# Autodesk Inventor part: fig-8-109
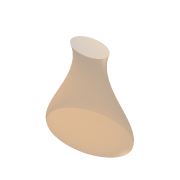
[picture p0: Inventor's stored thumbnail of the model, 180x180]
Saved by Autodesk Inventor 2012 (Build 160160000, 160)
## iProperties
Created: 2004-05
Part Number: fig-8-109
Document SubType Name: Modeling
Designer: CADCIM Technologies
Manufacturer: Standard
Standards Organization: Custom
Density: 1 g/cm^3
Material: Default
Author: CADCIM Technologies
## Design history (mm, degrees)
sketch "Sketch4"
  geometry: 1 further point; 1 other entity
  constraints: 2 other
workplane "Work Plane2"
sketch "Sketch5"
  geometry: 1 further point; 1 other entity
  constraints: 2 other
feature "LoftSrf1" sketch "Sketch5" dims "d4" = 20, "d5" = 110 deg, "d6" = 40, "d7" = 70 deg
patch "Boundary Patch1" dims "d8" = 0, "d9" = 0
body "Srf1"
body "Srf2"
other parameters: "d3" = 33.5
